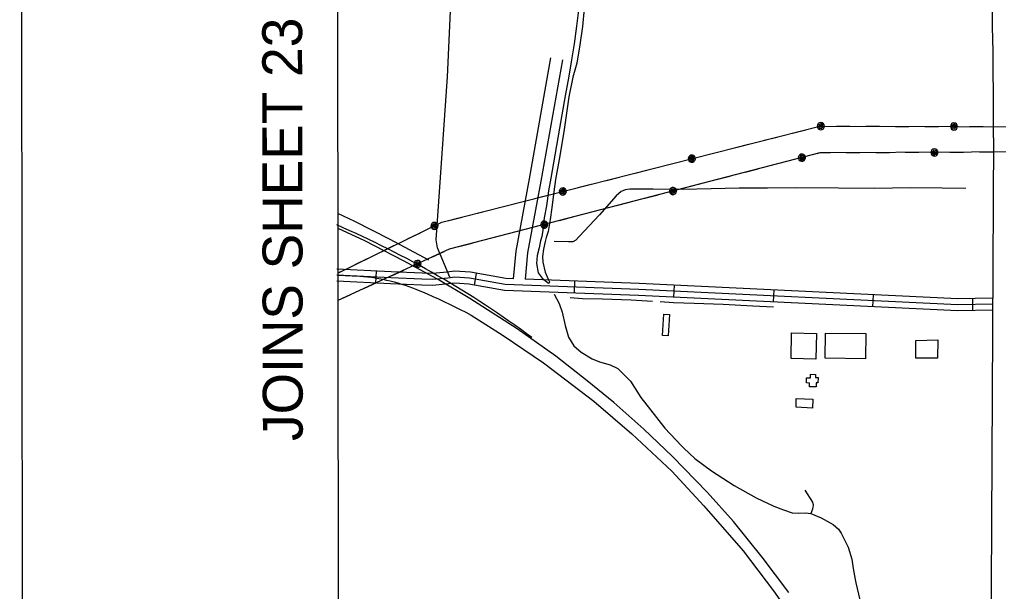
# Model space of a CAD drawing. Extents: x 3313447 to 3351316, y 703786 to 729172.
# Drawn here: x 3316782 to 3319238, y 723249 to 724684 of the extents above; entities that cross this region are included whole.
import ezdxf

# ---------------------------------------------------------------- set-up
doc = ezdxf.new("R2010")
doc.units = 0
for name, color, linetype in [('V-ANNO-SYMB', 7, 'Continuous'), ('V-ANNO-TEXT', 7, 'Continuous'), ('V-BLDG-OTLN', 7, 'Continuous'), ('V-DTCH-CNTR', 7, 'Continuous'), ('V-GRID-FRAM', 7, 'Continuous'), ('V-RAIL-TRAK', 7, 'Continuous'), ('V-ROAD-CNTR', 7, 'Continuous'), ('V-TOPO-SHOR', 7, 'Continuous'), ('V-UTIL-LINE', 7, 'Continuous')]:
    doc.layers.add(name, color=color, linetype=linetype)

msp = doc.modelspace()

# ---------------------------------------------------------------- linework, layer by layer
at = {"layer": 'V-ANNO-SYMB'}
msp.add_lwpolyline([(3316815.1, 704998.2), (3349898.2, 705046.3), (3349864.9, 727962.9), (3316781.7, 727914.8), (3316815.1, 704998.2)], dxfattribs=at)
at = {"layer": 'V-BLDG-OTLN'}
for points in [[(3318394.6, 723891.5), (3318398.2, 723944.4), (3318412.6, 723943.5), (3318409, 723890.5)], [(3318717.7, 723833), (3318718.9, 723897.4), (3318781.1, 723896.2), (3318779.9, 723831.8)], [(3318904.6, 723832.5), (3318803.2, 723833.8), (3318804.1, 723897.2), (3318905.5, 723895.9)], [(3319030.4, 723878.5), (3319085.5, 723880.1), (3319085, 723834.6), (3319031, 723834.4)], [(3318780.4, 723762.1), (3318763.5, 723762.5), (3318763.7, 723771.8), (3318756, 723772), (3318756.3, 723785.2), (3318766.3, 723785), (3318766.5, 723793.8), (3318779.3, 723793.5), (3318779.2, 723785.8), (3318785.2, 723785.7), (3318784.9, 723772.5), (3318780.6, 723772.6)], [(3318730.8, 723733.3), (3318772.4, 723731.1), (3318771, 723708.8), (3318730.7, 723711)]]:
    msp.add_lwpolyline(points, close=True, dxfattribs=at)
at = {"layer": 'V-DTCH-CNTR'}
for points in [[(3317861, 724037.4), (3317830.8, 724110.8), (3317826.7, 724131.5), (3317855.4, 724540.6), (3317886.2, 725220.7)], [(3317580.3, 724042.5), (3317616.1, 724041.2), (3317625.8, 724040.8), (3317635.5, 724040.1), (3317645.1, 724039.3), (3317654.8, 724038.3), (3317664.4, 724037.1), (3317674, 724035.7), (3317683.5, 724034), (3317693, 724032.2), (3317702.5, 724030.2), (3317711.9, 724028), (3317721.3, 724025.6), (3317730.6, 724023), (3317739.9, 724020.2), (3317749.1, 724017.2), (3317758.3, 724014), (3317767.4, 724010.6), (3317776.4, 724007), (3317790.6, 724001.3), (3317792.6, 724000.5), (3317804.7, 723995.5), (3317818.7, 723989.4), (3317832.6, 723983.1), (3317846.5, 723976.7), (3317860.3, 723970.1), (3317874, 723963.4), (3317887.6, 723956.4), (3317901.1, 723949.3), (3317914.6, 723942), (3317994.9, 723891.5), (3318096.6, 723822.5), (3318223, 723726.5), (3318317.8, 723644.3), (3318418, 723550.5), (3318499, 723463.5), (3318597.1, 723350.4), (3318673.9, 723250.4), (3318739.1, 723157.3)]]:
    msp.add_lwpolyline(points, dxfattribs=at)
at = {"layer": 'V-GRID-FRAM'}
msp.add_lwpolyline([(3317576.9, 727351), (3317595.4, 709166), (3349105.8, 709211.8), (3349071.4, 727396.8), (3317576.9, 727351)], dxfattribs=at)
at = {"layer": 'V-RAIL-TRAK'}
msp.add_lwpolyline([(3318711.7, 723246), (3318645.4, 723334.9), (3318573.2, 723424.4), (3318507.4, 723497.9), (3318420, 723587.4), (3318348.3, 723656.3), (3318273, 723723), (3318206.1, 723777), (3318127, 723839.6), (3318030, 723907.9), (3317911.9, 723984.3), (3317830.2, 724032.5), (3317829.1, 724033.1), (3317745.3, 724078.7), (3317647.7, 724128.6), (3317581.2, 724159.4), (3317580.2, 724159.9)], dxfattribs=at)
at = {"layer": 'V-ROAD-CNTR'}
for p, q in [((3317675.9, 724022.5), (3317677.4, 724052.5)), ((3317923.3, 724017.5), (3317928.4, 724047.1)), ((3318174, 723997.7), (3318175.2, 724027.7)), ((3318423.7, 723987.3), (3318425.1, 724017.2)), ((3318673.4, 723975.3), (3318674.8, 724005.3)), ((3318923.1, 723963.4), (3318924.5, 723993.4)), ((3319173.8, 723953.8), (3319173.4, 723983.8))]:
    msp.add_line(p, q, dxfattribs=at)
for points in [[(3318114.3, 724588.4), (3318060.3, 724284.1), (3318026.9, 724102.5), (3318020.2, 724033.7)], [(3318143.8, 724583.1), (3318089.8, 724278.7), (3318056.6, 724098.3), (3318050.2, 724032.5)], [(3319225.7, 724387.2), (3319219.9, 723260.5), (3319216.9, 722089), (3319220.7, 721173.5), (3319213.5, 720516.4), (3319203, 719335.9), (3319201.9, 718251.3), (3319198, 717354.7), (3319193.3, 716367.9), (3319200.9, 715645.2)], [(3318020.2, 724033.7), (3318002.1, 724034.3), (3317912.8, 724049.7), (3317873.1, 724052.9), (3317854.3, 724050.3), (3317817.9, 724046.7), (3317791.9, 724047.6), (3317714, 724050.6), (3317577.9, 724057.7)], [(3319223.6, 723969.5), (3319136, 723968.2), (3318335.5, 724006.5), (3318000.5, 724019.4), (3317910.9, 724034.8), (3317873.5, 724037.8), (3317856.1, 724035.4), (3317818.4, 724031.6), (3317791.4, 724032.6), (3317713.3, 724035.6), (3317577.9, 724042.7)], [(3319223.4, 723984.5), (3319136.3, 723983.3), (3318336.1, 724021.5), (3318050.2, 724032.5)], [(3319223.8, 723954.5), (3319135.8, 723953.2), (3318334.8, 723991.5), (3317998.9, 724004.4), (3317909.1, 724019.9), (3317874, 724022.8), (3317857.9, 724020.5), (3317818.9, 724016.6), (3317790.8, 724017.6), (3317712.6, 724020.6), (3317578, 724027.7)]]:
    msp.add_lwpolyline(points, dxfattribs=at)
for centre, radius, start, end in [((3305637.9, 724414.3), 13587.8, 359.8855, 4.06266), ((3316586.2, 721886.3), 2488.4, 53.4717, 66.515)]:
    msp.add_arc(centre, radius, start, end, dxfattribs=at)
at = {"layer": 'V-TOPO-SHOR'}
for points in [[(3318185, 724714.3), (3318179, 724667.8), (3318173.4, 724622.8), (3318165.4, 724578.4), (3318159.8, 724542.3), (3318150.7, 724492.4), (3318136.4, 724411.9), (3318124.5, 724343.8), (3318114.7, 724286), (3318108.8, 724254.4), (3318103.5, 724216.6), (3318098.3, 724186.6), (3318094.4, 724155.3), (3318092, 724139.9), (3318088.5, 724128.9), (3318085.7, 724111.3), (3318080.5, 724092.1), (3318078.7, 724072.1), (3318083.2, 724048.7), (3318093.4, 724034.9), (3318108.8, 724022.7)], [(3318198.8, 724711.8), (3318194.2, 724666.8), (3318187.5, 724620.7), (3318179.8, 724574.6), (3318170.1, 724539.5), (3318160.3, 724490), (3318148.4, 724408.5), (3318137.6, 724341.7), (3318126.4, 724282.6), (3318122.2, 724251.6), (3318117.6, 724212.1), (3318112.7, 724182.5), (3318108.2, 724151.9), (3318103.3, 724137.1), (3318100.2, 724126.8), (3318096, 724108.2), (3318093.9, 724089.3), (3318094.6, 724074.8), (3318100.7, 724050), (3318107.9, 724032.8), (3318111.8, 724026.1), (3318110.5, 724022.7), (3318108.8, 724022.7)], [(3319156.3, 724260.3), (3319096.8, 724261.2), (3319016.9, 724261.4), (3318927, 724259.9), (3318837, 724260.8), (3318730.5, 724261.4), (3318658.6, 724260.9), (3318587.7, 724260.8), (3318517.5, 724259.2), (3318444.5, 724257.4), (3318371.2, 724258.2), (3318313.1, 724258.4), (3318301.3, 724257), (3318295.1, 724254.6), (3318291.3, 724252.2), (3318278.8, 724241.9), (3318236.5, 724193.6), (3318186.2, 724139.4), (3318177.9, 724130.1), (3318170.3, 724126.6), (3318159.2, 724126.3), (3318123.4, 724126.7)], [(3317808.4, 724080.6), (3317712, 724132.2), (3317623.3, 724176.9), (3317580.1, 724197.6)], [(3318123.5, 723994.9), (3318136, 723971.5), (3318143.3, 723949.9), (3318150.6, 723916.1), (3318159.5, 723887), (3318172.7, 723865.3), (3318191.1, 723848.9), (3318218.5, 723832.4), (3318237, 723825), (3318263.9, 723817.5), (3318282.9, 723808), (3318314.5, 723776.2), (3318340.8, 723735.5), (3318365, 723704.2), (3318400.8, 723658.7), (3318442.4, 723614.3), (3318448.9, 723608.1)], [(3318369.8, 723976.4), (3318316.3, 723979.4), (3318244.4, 723982), (3318194.1, 723983.2), (3318163.3, 723985.6)], [(3318673.1, 723962), (3318621.5, 723964.5), (3318547.1, 723968.5), (3318474.2, 723971.8), (3318422.6, 723973.3), (3318388.8, 723975.3)], [(3318448.9, 723608.1), (3318476.1, 723582.5), (3318518.3, 723551.2), (3318575.2, 723514.6), (3318630.1, 723483.8), (3318674.4, 723463.1), (3318698.7, 723453.6), (3318720.3, 723446.1), (3318737.3, 723444.9), (3318753.5, 723445.7), (3318767.3, 723444.1), (3318792.9, 723433.5), (3318823.5, 723417), (3318836.4, 723404.6), (3318843, 723395), (3318848.5, 723385), (3318861.1, 723359.7), (3318870, 723329.5), (3318873.6, 723306.3), (3318878.3, 723278.3), (3318880, 723270.2), (3318889.8, 723227.6)], [(3318752, 723502.9), (3318771.4, 723472.9), (3318773, 723465.1), (3318771.2, 723455.4), (3318767.3, 723444.1)]]:
    msp.add_lwpolyline(points, dxfattribs=at)
at = {"layer": 'V-UTIL-LINE'}
for points in [[(3318792.4, 724416.5), (3318790.8, 724418.9), (3318789.9, 724416.7), (3318791.6, 724414.5), (3318794.5, 724414.8), (3318794.6, 724418.2), (3318791.4, 724421.6), (3318787.5, 724419.8), (3318786.2, 724415.1), (3318789.3, 724411.7), (3318793.6, 724410.7), (3318797.4, 724413.8), (3318797.7, 724419.3), (3318792.4, 724425.5), (3318789, 724424.8), (3318786, 724422.9), (3318784.1, 724420), (3318783.4, 724416.5), (3318784.1, 724413.1), (3318786, 724410.1), (3318788.9, 724408.2), (3318792.4, 724407.5), (3318795.8, 724408.2), (3318798.7, 724410.1), (3318800.7, 724413), (3318801.4, 724416.5), (3318800.7, 724419.9), (3318798.8, 724422.8), (3318795.8, 724424.8), (3318792.4, 724425.5)], [(3319126.4, 724415.7), (3319124.8, 724418.1), (3319123.9, 724415.9), (3319125.6, 724413.7), (3319128.5, 724414), (3319128.6, 724417.4), (3319125.4, 724420.8), (3319121.5, 724419.1), (3319120.2, 724414.4), (3319123.3, 724411), (3319127.6, 724410), (3319131.4, 724413), (3319131.7, 724418.5), (3319126.4, 724424.7), (3319123, 724424.1), (3319120, 724422.1), (3319118.1, 724419.2), (3319117.4, 724415.8), (3319118.1, 724412.3), (3319120, 724409.4), (3319122.9, 724407.4), (3319126.4, 724406.7), (3319129.8, 724407.4), (3319132.7, 724409.4), (3319134.7, 724412.3), (3319135.4, 724415.7), (3319134.7, 724419.2), (3319132.8, 724422.1), (3319129.8, 724424), (3319126.4, 724424.7)], [(3317580.3, 724047.8), (3317841.3, 724175.4), (3318789.6, 724416.5), (3320526.2, 724412.6), (3321901.4, 724347.2)], [(3318721.5, 724399.2), (3318754.5, 724407.6)], [(3318831.4, 724416.4), (3318865.4, 724416.3)], [(3318905.4, 724416.2), (3318939.4, 724416.2)], [(3318979.4, 724416.1), (3319013.4, 724416)], [(3319053.4, 724415.9), (3319087.4, 724415.8)], [(3319165.4, 724415.7), (3319199.4, 724415.6)], [(3318649.8, 724381), (3318682.8, 724389.3)], [(3321895.2, 724298.5), (3320342.6, 724354.5), (3319931.2, 724354.3), (3318789.9, 724349.2), (3317860, 724107.6), (3317580.3, 723978.6)], [(3318506.4, 724344.5), (3318539.3, 724352.9)], [(3318578.1, 724362.7), (3318611.1, 724371.1)], [(3318816.2, 724349.3), (3318789.9, 724349.2), (3318782.4, 724347.2)], [(3318890.2, 724349.6), (3318856.2, 724349.5)], [(3318964.2, 724350), (3318930.2, 724349.8)], [(3319038.2, 724350.3), (3319004.2, 724350.1)], [(3319077.2, 724350.5), (3319078.9, 724348.1), (3319079.7, 724350.3), (3319078, 724352.5), (3319075.1, 724352.2), (3319075, 724348.8), (3319078.2, 724345.4), (3319082.1, 724347.2), (3319083.4, 724351.9), (3319080.3, 724355.3), (3319075.9, 724356.2), (3319072.2, 724353.1), (3319071.9, 724347.6), (3319077.2, 724341.5), (3319080.7, 724342.2), (3319083.6, 724344.1), (3319085.5, 724347.1), (3319086.2, 724350.5), (3319085.5, 724353.9), (3319083.5, 724356.9), (3319080.6, 724358.8), (3319077.2, 724359.5), (3319073.7, 724358.8), (3319070.8, 724356.8), (3319068.9, 724353.9), (3319068.2, 724350.4), (3319068.9, 724347), (3319070.9, 724344.1), (3319073.8, 724342.1), (3319077.2, 724341.5)], [(3319150.2, 724350.8), (3319116.2, 724350.6)], [(3319224.2, 724351.1), (3319190.2, 724351)], [(3318397.8, 724316.9), (3318430.8, 724325.3)], [(3318468.6, 724334.9), (3318466.4, 724336.8), (3318466.2, 724334.5), (3318468.3, 724332.7), (3318471, 724333.7), (3318470.4, 724337.1), (3318466.4, 724339.6), (3318463.1, 724336.9), (3318463, 724332), (3318466.8, 724329.5), (3318471.3, 724329.6), (3318474.1, 724333.5), (3318473.1, 724338.9), (3318466.4, 724343.6), (3318463.2, 724342.1), (3318460.9, 724339.5), (3318459.7, 724336.2), (3318459.9, 724332.7), (3318461.4, 724329.5), (3318464, 724327.1), (3318467.3, 724326), (3318470.8, 724326.2), (3318474, 724327.7), (3318476.3, 724330.3), (3318477.5, 724333.6), (3318477.3, 724337.1), (3318475.8, 724340.3), (3318473.2, 724342.6), (3318469.9, 724343.8), (3318466.4, 724343.6)], [(3318707, 724327.6), (3318674, 724319.1)], [(3318744.7, 724337.4), (3318746.9, 724335.6), (3318747.1, 724337.9), (3318745, 724339.6), (3318742.3, 724338.6), (3318743, 724335.2), (3318746.9, 724332.8), (3318750.2, 724335.5), (3318750.3, 724340.3), (3318746.5, 724342.8), (3318742, 724342.7), (3318739.2, 724338.8), (3318740.3, 724333.4), (3318747, 724328.7), (3318750.1, 724330.3), (3318752.5, 724332.9), (3318753.6, 724336.2), (3318753.4, 724339.7), (3318751.9, 724342.9), (3318749.3, 724345.2), (3318746, 724346.4), (3318742.4, 724346.2), (3318739.3, 724344.6), (3318736.9, 724342), (3318735.8, 724338.7), (3318736, 724335.2), (3318737.5, 724332), (3318740.1, 724329.7), (3318743.5, 724328.5), (3318747, 724328.7)], [(3318326.1, 724298.7), (3318359.1, 724307)], [(3318635.3, 724309), (3318602.4, 724300.5)], [(3318254.4, 724280.4), (3318287.4, 724288.8)], [(3318563.7, 724290.4), (3318530.8, 724281.9)], [(3318144.9, 724252.6), (3318142.7, 724254.5), (3318142.5, 724252.2), (3318144.6, 724250.4), (3318147.3, 724251.4), (3318146.7, 724254.8), (3318142.7, 724257.3), (3318139.4, 724254.6), (3318139.3, 724249.7), (3318143.1, 724247.2), (3318147.6, 724247.3), (3318150.4, 724251.2), (3318149.4, 724256.6), (3318142.7, 724261.3), (3318139.5, 724259.8), (3318137.2, 724257.2), (3318136, 724253.9), (3318136.2, 724250.4), (3318137.7, 724247.2), (3318140.3, 724244.8), (3318143.6, 724243.7), (3318147.1, 724243.9), (3318150.3, 724245.4), (3318152.6, 724248), (3318153.8, 724251.3), (3318153.6, 724254.8), (3318152.1, 724258), (3318149.5, 724260.3), (3318146.2, 724261.5), (3318142.7, 724261.3)], [(3318182.7, 724262.2), (3318215.6, 724270.6)], [(3318421.4, 724253.4), (3318423.6, 724251.6), (3318423.9, 724253.9), (3318421.7, 724255.6), (3318419, 724254.6), (3318419.7, 724251.2), (3318423.7, 724248.8), (3318427, 724251.5), (3318427.1, 724256.3), (3318423.2, 724258.8), (3318418.8, 724258.7), (3318415.9, 724254.8), (3318417, 724249.4), (3318423.7, 724244.7), (3318426.9, 724246.3), (3318429.2, 724248.9), (3318430.4, 724252.2), (3318430.2, 724255.7), (3318428.6, 724258.9), (3318426, 724261.2), (3318422.7, 724262.4), (3318419.2, 724262.2), (3318416, 724260.6), (3318413.7, 724258), (3318412.5, 724254.7), (3318412.7, 724251.2), (3318414.3, 724248), (3318416.9, 724245.7), (3318420.2, 724244.5), (3318423.7, 724244.7)], [(3318492.1, 724271.8), (3318459.2, 724263.2)], [(3318074.1, 724234.6), (3318107.1, 724243)], [(3318312.1, 724225), (3318279.2, 724216.5)], [(3318383.7, 724243.6), (3318350.8, 724235.1)], [(3317930.7, 724198.1), (3317963.7, 724206.5)], [(3318002.4, 724216.4), (3318035.4, 724224.7)], [(3318240.5, 724206.4), (3318207.5, 724197.9)], [(3317859, 724179.9), (3317891.9, 724188.3)], [(3318098.2, 724169.4), (3318100.4, 724167.6), (3318100.6, 724169.9), (3318098.5, 724171.6), (3318095.7, 724170.6), (3318096.4, 724167.3), (3318100.4, 724164.8), (3318103.7, 724167.5), (3318103.8, 724172.3), (3318100, 724174.9), (3318095.5, 724174.7), (3318092.7, 724170.8), (3318093.7, 724165.4), (3318100.4, 724160.7), (3318103.6, 724162.3), (3318105.9, 724164.9), (3318107.1, 724168.2), (3318106.9, 724171.7), (3318105.4, 724174.9), (3318102.7, 724177.2), (3318099.4, 724178.4), (3318095.9, 724178.2), (3318092.8, 724176.6), (3318090.4, 724174), (3318089.3, 724170.7), (3318089.5, 724167.2), (3318091, 724164), (3318093.6, 724161.7), (3318096.9, 724160.5), (3318100.4, 724160.7)], [(3318168.8, 724187.8), (3318135.9, 724179.3)], [(3317822.7, 724166.3), (3317820.2, 724167.7), (3317820.4, 724165.4), (3317822.8, 724164.1), (3317825.3, 724165.6), (3317824, 724168.8), (3317819.6, 724170.4), (3317816.9, 724167.1), (3317817.7, 724162.3), (3317822, 724160.6), (3317826.3, 724161.7), (3317828.3, 724166.1), (3317826.2, 724171.1), (3317818.7, 724174.4), (3317815.9, 724172.2), (3317814.2, 724169.2), (3317813.7, 724165.7), (3317814.6, 724162.3), (3317816.7, 724159.5), (3317819.8, 724157.8), (3317823.2, 724157.3), (3317826.6, 724158.2), (3317829.4, 724160.3), (3317831.2, 724163.3), (3317831.7, 724166.8), (3317830.8, 724170.2), (3317828.6, 724173), (3317825.6, 724174.8), (3317822.1, 724175.2), (3317818.7, 724174.4)], [(3318060.4, 724159.6), (3318027.5, 724151.1)], [(3317757.1, 724134.2), (3317787.6, 724149.1)], [(3317988.8, 724141), (3317955.9, 724132.5)], [(3317690.6, 724101.7), (3317721.2, 724116.6)], [(3317917.2, 724122.4), (3317884.3, 724113.9)], [(3317624.1, 724069.2), (3317654.7, 724084.1)], [(3317780.2, 724070.7), (3317782.6, 724069.3), (3317782.5, 724071.6), (3317780.1, 724072.9), (3317777.6, 724071.4), (3317778.8, 724068.3), (3317783.2, 724066.6), (3317786, 724069.8), (3317785.2, 724074.6), (3317781, 724076.4), (3317776.6, 724075.4), (3317774.5, 724071.1), (3317776.5, 724066), (3317783.9, 724062.6), (3317786.8, 724064.6), (3317788.6, 724067.6), (3317789.2, 724071.1), (3317788.3, 724074.5), (3317786.3, 724077.4), (3317783.3, 724079.2), (3317779.8, 724079.7), (3317776.4, 724078.9), (3317773.6, 724076.9), (3317771.7, 724073.9), (3317771.2, 724070.4), (3317772, 724067), (3317774.1, 724064.1), (3317777.1, 724062.3), (3317780.5, 724061.8), (3317783.9, 724062.6)], [(3317846.5, 724101.3), (3317815.6, 724087.1)], [(3317744.7, 724054.4), (3317713.9, 724040.2)], [(3317580.3, 724047.8), (3317588.2, 724051.6)], [(3317580.3, 724047.8), (3317580.3, 724047.8)], [(3317580.3, 724047.8), (3317580.3, 724047.8)], [(3317677.5, 724023.4), (3317646.7, 724009.2)], [(3317610.3, 723992.5), (3317580.3, 723978.6)], [(3317580.3, 723978.6), (3317580.3, 723978.6)], [(3317580.3, 723978.6), (3317580.3, 723978.6)]]:
    msp.add_lwpolyline(points, dxfattribs=at)

# ---------------------------------------------------------------- texts
at = {"layer": 'V-ANNO-TEXT'}
msp.add_text('JOINS SHEET 23', height=100, rotation=90.0833, dxfattribs=at).set_placement((3317492.2, 723626.3))

doc.saveas('drawing.dxf')
